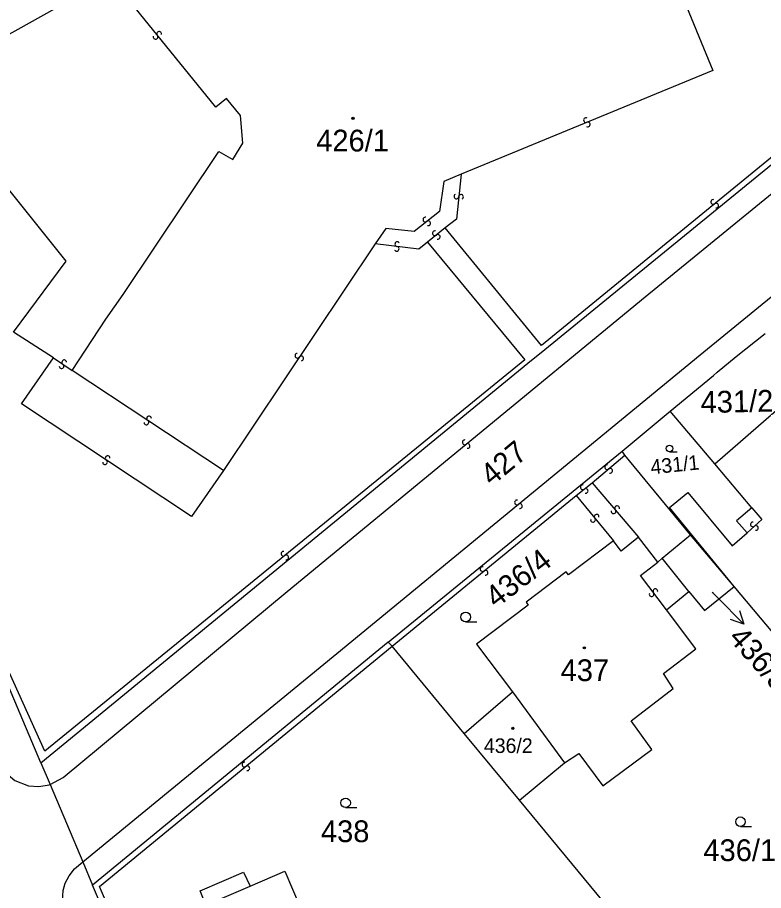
# Model space of a CAD drawing. Extents: x -600391 to -599491, y -1160176 to -1159402.
# Drawn here: x -599968.2 to -599909.8, y -1159960.8 to -1159892.6 of the extents above; entities that cross this region are included whole.
import ezdxf

# ---------------------------------------------------------------- set-up
doc = ezdxf.new("R2010")
doc.units = 0
for name, color, linetype in [('Level 1', 7, 'Continuous'), ('Level 13', 7, 'Continuous'), ('Level 3', 7, 'Continuous'), ('Level 4', 7, 'Continuous'), ('Level 5', 7, 'Continuous'), ('Level 57', 7, 'Continuous')]:
    doc.layers.add(name, color=color, linetype=linetype)

msp = doc.modelspace()

# ---------------------------------------------------------------- linework, layer by layer
at = {"layer": 'Level 1'}
for points in [[(-599973.76, -1159893.33), (-599972.37, -1159895.85), (-599965.19, -1159891.85)], [(-599966.31, -1159950.82), (-599970.49, -1159941), (-599975.15, -1159930.49), (-599979.88, -1159920.04), (-599984.4, -1159910.19), (-599988.54, -1159901.64), (-599992.81, -1159893.05)], [(-599966.31, -1159950.82), (-599928.23, -1159919.57), (-599926.91, -1159918.5), (-599899.82, -1159896.42), (-599899.51, -1159896.14), (-599899.24, -1159895.74), (-599899.13, -1159895.39), (-599899.08, -1159894.99), (-599899.17, -1159894.48), (-599899.43, -1159893.99)], [(-599917.1, -1159923.33), (-599913.73, -1159920.54), (-599913.44, -1159920.29), (-599911.95, -1159919.06), (-599909.67, -1159917.25)], [(-599913.62, -1159927.46), (-599906.39, -1159921.18)], [(-599920.85, -1159926.45), (-599917.1, -1159923.33)], [(-599913.62, -1159927.46), (-599917.1, -1159923.33)], [(-599939.16, -1159941.39), (-599920.85, -1159926.45)], [(-599920.64, -1159926.78), (-599920.85, -1159926.45)], [(-599915.51, -1159933), (-599920.64, -1159926.78)], [(-599910.73, -1159930.89), (-599913.62, -1159927.46)], [(-599912.09, -1159937.04), (-599917.16, -1159930.87), (-599915.72, -1159929.68), (-599912.25, -1159933.86), (-599911.09, -1159932.83)], [(-599910.73, -1159930.89), (-599911.91, -1159931.9), (-599911.09, -1159932.83)], [(-599919.59, -1159933.17), (-599920.93, -1159934.27), (-599921.55, -1159933.47)], [(-599918.06, -1159935.14), (-599919.59, -1159933.17)], [(-599917.74, -1159934.83), (-599915.51, -1159933)], [(-599912.09, -1159937.04), (-599915.51, -1159933)], [(-599921.55, -1159933.47), (-599925.05, -1159936.13), (-599925.23, -1159935.89), (-599928.36, -1159938.26), (-599928.22, -1159938.49), (-599932.25, -1159941.55), (-599929.45, -1159945.28)], [(-599917.74, -1159934.83), (-599918.06, -1159935.14)], [(-599915.64, -1159937.43), (-599917.74, -1159934.83)], [(-599915.64, -1159937.43), (-599914.41, -1159938.92), (-599912.09, -1159937.04)], [(-599909.09, -1159940.63), (-599912.09, -1159937.04)], [(-599917.39, -1159938.87), (-599915.64, -1159937.43)], [(-599925.37, -1159950.82), (-599924.25, -1159950.09), (-599922.38, -1159952.63), (-599918.55, -1159949.77), (-599920.17, -1159947.54), (-599916.87, -1159945.01), (-599917.63, -1159943.85), (-599915.1, -1159941.91), (-599917.39, -1159938.87)], [(-599939.16, -1159941.39), (-599962.28, -1159960.37)], [(-599938.86, -1159941.7), (-599939.16, -1159941.39)], [(-599933.21, -1159948.52), (-599938.86, -1159941.7)], [(-599933.21, -1159948.52), (-599929.45, -1159945.28)], [(-599929.45, -1159945.28), (-599925.37, -1159950.82)], [(-599928.88, -1159953.75), (-599933.21, -1159948.52)], [(-599966.31, -1159950.82), (-599965.6, -1159952.51)], [(-599928.88, -1159953.75), (-599925.37, -1159950.82)], [(-599965.6, -1159952.51), (-599963.03, -1159958.57)], [(-599922.31, -1159961.69), (-599928.88, -1159953.75)], [(-599963.03, -1159958.57), (-599962.28, -1159960.37)], [(-599953.41, -1159961.95), (-599953.86, -1159960.82), (-599950.47, -1159959.37), (-599949.96, -1159960.45)], [(-599949.96, -1159960.45), (-599947.24, -1159959.3), (-599946.05, -1159962.1)], [(-599955.61, -1159975.93), (-599962.28, -1159960.37)]]:
    msp.add_lwpolyline(points, dxfattribs=at)
at = {"layer": 'Level 13'}
for centre, start, end in [((-599957.066, -1159893.835), 346.13317, 218.72317), ((-599957.354, -1159894.065), 166.34762, 38.44562), ((-599923.689, -1159900.58), 59.54427, 292.13427), ((-599923.551, -1159900.921), 239.75872, 111.85672), ((-599933.823, -1159906.541), 121.33521, 353.92521), ((-599933.457, -1159906.58), 301.54967, 173.64767), ((-599913.736, -1159906.977), 76.43962, 309.02962), ((-599913.505, -1159907.264), 256.65408, 128.75207), ((-599936.253, -1159908.355), 75.25187, 307.84187), ((-599936.028, -1159908.646), 255.46633, 127.56432), ((-599935.506, -1159909.417), 76.47029, 309.06029), ((-599935.274, -1159909.704), 256.68474, 128.78274), ((-599938.494, -1159910.643), 210.51671, 82.61471), ((-599938.447, -1159910.277), 30.30225, 262.89225), ((-599946.262, -1159918.997), 93.30428, 325.89428), ((-599964.496, -1159919.508), 3.59342, 235.69142), ((-599945.958, -1159919.204), 273.51873, 145.61673), ((-599964.703, -1159919.813), 183.37896, 55.96896), ((-599958.063, -1159924.213), 183.92968, 56.02768), ((-599957.858, -1159923.907), 3.71522, 236.30522), ((-599933.176, -1159925.766), 76.77776, 308.87575), ((-599932.944, -1159926.053), 256.5633, 129.1533), ((-599961.098, -1159927.007), 3.58776, 236.17776), ((-599961.303, -1159927.313), 183.80222, 55.90022), ((-599922.037, -1159927.707), 77.26625, 309.36425), ((-599921.803, -1159927.992), 257.05179, 129.64179), ((-599923.945, -1159929.275), 76.31094, 308.40894), ((-599923.715, -1159929.564), 256.09649, 128.68649), ((-599929.086, -1159930.466), 76.78716, 308.88516), ((-599928.854, -1159930.753), 256.5727, 129.1627), ((-599921.541, -1159931.159), 167.50324, 40.09324), ((-599921.258, -1159930.922), 347.7177, 219.81569), ((-599923.143, -1159931.816), 166.48292, 39.07292), ((-599922.856, -1159931.584), 346.69738, 218.79538), ((-599910.642, -1159932.182), 78.72991, 311.31991), ((-599910.399, -1159932.459), 258.94436, 131.04236), ((-599947.356, -1159934.477), 76.33703, 308.92703), ((-599947.125, -1159934.764), 256.55148, 128.64948), ((-599931.775, -1159935.676), 76.61447, 308.71247), ((-599931.544, -1159935.963), 256.40002, 128.99002), ((-599918.263, -1159937.41), 344.23135, 216.82135), ((-599918.558, -1159937.63), 164.44581, 36.5438), ((-599950.406, -1159950.956), 76.79423, 308.89222), ((-599950.174, -1159951.243), 256.57977, 129.16977)]:
    msp.add_arc(centre, 0.184, start, end, dxfattribs=at)
at = {"layer": 'Level 3'}
for points in [[(-600033.38, -1159823.63), (-600033.12, -1159824.1), (-600010.83, -1159864.69), (-600004.5, -1159876.7), (-599993.64, -1159898.18), (-599985.83, -1159914.4), (-599969.99, -1159949.74), (-599969.77, -1159950.61), (-599969.2, -1159951.5), (-599968.36, -1159952.21), (-599967.29, -1159952.61), (-599966.47, -1159952.67), (-599965.66, -1159952.53), (-599965.6, -1159952.51)], [(-599923.93, -1159864.42), (-599912.61, -1159878.33), (-599899.66, -1159894.2), (-599899.47, -1159894.52), (-599899.39, -1159894.94), (-599899.46, -1159895.33), (-599899.59, -1159895.61), (-599899.8, -1159895.87), (-599900.08, -1159896.05), (-599927.16, -1159918.2), (-599934.7, -1159908.99)], [(-599919.16, -1159883.57), (-599913.77, -1159896.69), (-599933.46, -1159904.8)], [(-599963.86, -1159920.16), (-599961.23, -1159916.15), (-599959.88, -1159914.2), (-599952.41, -1159903.03), (-599951.32, -1159903.66), (-599950.53, -1159902.39), (-599950.7, -1159900.21), (-599951.8, -1159898.9), (-599952.65, -1159899.58), (-599961.76, -1159888.32)], [(-599936.08, -1159910.12), (-599928.46, -1159919.31), (-599966.02, -1159949.92), (-599970.15, -1159940.79), (-599974.83, -1159930.3), (-599979.55, -1159919.91), (-599984.14, -1159909.96), (-599988.22, -1159901.32), (-599992.49, -1159892.92)], [(-599965.34, -1159919.17), (-599968.46, -1159917.16), (-599964.35, -1159911.61), (-599976.85, -1159896), (-599973.76, -1159893.33)], [(-599965.6, -1159952.51), (-599964.58, -1159951.97), (-599947.07, -1159937.42), (-599919.05, -1159914.4), (-599898.21, -1159897.38), (-599897.38, -1159896.51)], [(-599963.03, -1159958.57), (-599943.17, -1159942.28), (-599914.77, -1159918.94), (-599894.25, -1159902.16), (-599893.41, -1159901.39)], [(-599933.46, -1159904.8), (-599934.82, -1159905.39), (-599935.14, -1159907.72), (-599937.13, -1159909.28), (-599939.33, -1159909.04), (-599940.17, -1159910.25)], [(-599933.46, -1159904.8), (-599933.82, -1159908.33), (-599934.7, -1159908.99)], [(-599934.7, -1159908.99), (-599936.08, -1159910.12)], [(-599940.17, -1159910.25), (-599952.05, -1159927.96)], [(-599936.08, -1159910.12), (-599936.76, -1159910.66), (-599940.17, -1159910.25)], [(-599952.05, -1159927.96), (-599954.55, -1159931.57), (-599967.84, -1159922.75), (-599965.34, -1159919.17)], [(-599965.34, -1159919.17), (-599963.86, -1159920.16)], [(-599952.05, -1159927.96), (-599963.86, -1159920.16)], [(-599923.2, -1159928.92), (-599920.64, -1159926.78)], [(-599924.45, -1159929.93), (-599923.2, -1159928.92)], [(-599923.2, -1159928.92), (-599919.59, -1159933.17)], [(-599938.86, -1159941.7), (-599924.45, -1159929.93)], [(-599924.45, -1159929.93), (-599921.55, -1159933.47)], [(-599910.73, -1159930.89), (-599909.94, -1159931.81), (-599911.09, -1159932.83)], [(-599917.39, -1159938.87), (-599919.43, -1159936.17), (-599918.06, -1159935.14)], [(-599955.18, -1159975.74), (-599961.73, -1159960.5), (-599938.86, -1159941.7)], [(-599916.7, -1160066.63), (-599917.11, -1160066.76), (-599917.67, -1160067), (-599918.32, -1160067.07), (-599918.8, -1160066.99), (-599919.27, -1160066.8), (-599919.69, -1160066.51), (-599919.99, -1160066.19), (-599936.81, -1160026.95), (-599950.41, -1159995.05), (-599964.44, -1159962.51), (-599964.64, -1159961.64), (-599964.57, -1159960.81), (-599964.41, -1159960.23), (-599964.11, -1159959.66), (-599963.69, -1159959.11), (-599963.03, -1159958.57)], [(-599953.41, -1159961.95), (-599949.96, -1159960.45)]]:
    msp.add_lwpolyline(points, dxfattribs=at)
at = {"layer": 'Level 5'}
for p, q in [((-599917.16, -1159926.5), (-599916.565, -1159926.5)), ((-599933.1, -1159939.8), (-599932.225, -1159939.8)), ((-599942.49, -1159954.32), (-599941.615, -1159954.32)), ((-599911.61, -1159955.8), (-599910.735, -1159955.8))]:
    msp.add_line(p, q, dxfattribs=at)
for centre, radius in [((-599941.9, -1159900.43), 0.09), ((-599941.9, -1159900.43), 0.0521), ((-599917.16, -1159926.245), 0.255), ((-599933.1, -1159939.425), 0.375), ((-599923.81, -1159941.83), 0.09), ((-599923.81, -1159941.83), 0.0521), ((-599929.41, -1159948.13), 0.09), ((-599929.41, -1159948.13), 0.0521), ((-599942.49, -1159953.945), 0.375), ((-599911.61, -1159955.425), 0.375)]:
    msp.add_circle(centre, radius, dxfattribs=at)
at = {"layer": 'Level 57'}
for p, q in [((-599913.83, -1159937.49), (-599913.466, -1159937.853)), ((-599913.466, -1159937.853), (-599911.34, -1159939.97))]:
    msp.add_line(p, q, dxfattribs=at)
msp.add_lwpolyline([(-599911.696, -1159938.91), (-599911.34, -1159939.97), (-599912.402, -1159939.619)], dxfattribs=at)

# ---------------------------------------------------------------- texts
at = {"layer": 'Level 4'}
for s, height, p in [('426/1', 1.7, (-599944.787, -1159903.03)), ('437', 1.7, (-599925.676, -1159944.43)), ('436/2', 1.14, (-599931.674, -1159950.05)), ('438', 1.7, (-599944.419, -1159957.02)), ('436/1', 1.7, (-599914.509, -1159958.5))]:
    msp.add_text(s, height=height, dxfattribs=at).set_placement(p)
for s, height, rotation, p in [('431/2', 1.7, 1.19997, (-599914.713, -1159923.48)), ('427', 1.7, 39.6, (-599931.061, -1159929.238)), ('431/1', 1.14, 5.76108, (-599918.583, -1159928.267)), ('436/4', 1.7, 37.8, (-599930.724, -1159938.784)), ('436/3', 0.1, 311.4, (-599913.83, -1159937.49))]:
    msp.add_text(s, height=height, rotation=rotation, dxfattribs=at).set_placement(p)
at = {"layer": 'Level 57'}
msp.add_text('436/3', height=1.7, rotation=311.4, dxfattribs=at).set_placement((-599912.615, -1159941.094))

doc.saveas('drawing.dxf')
